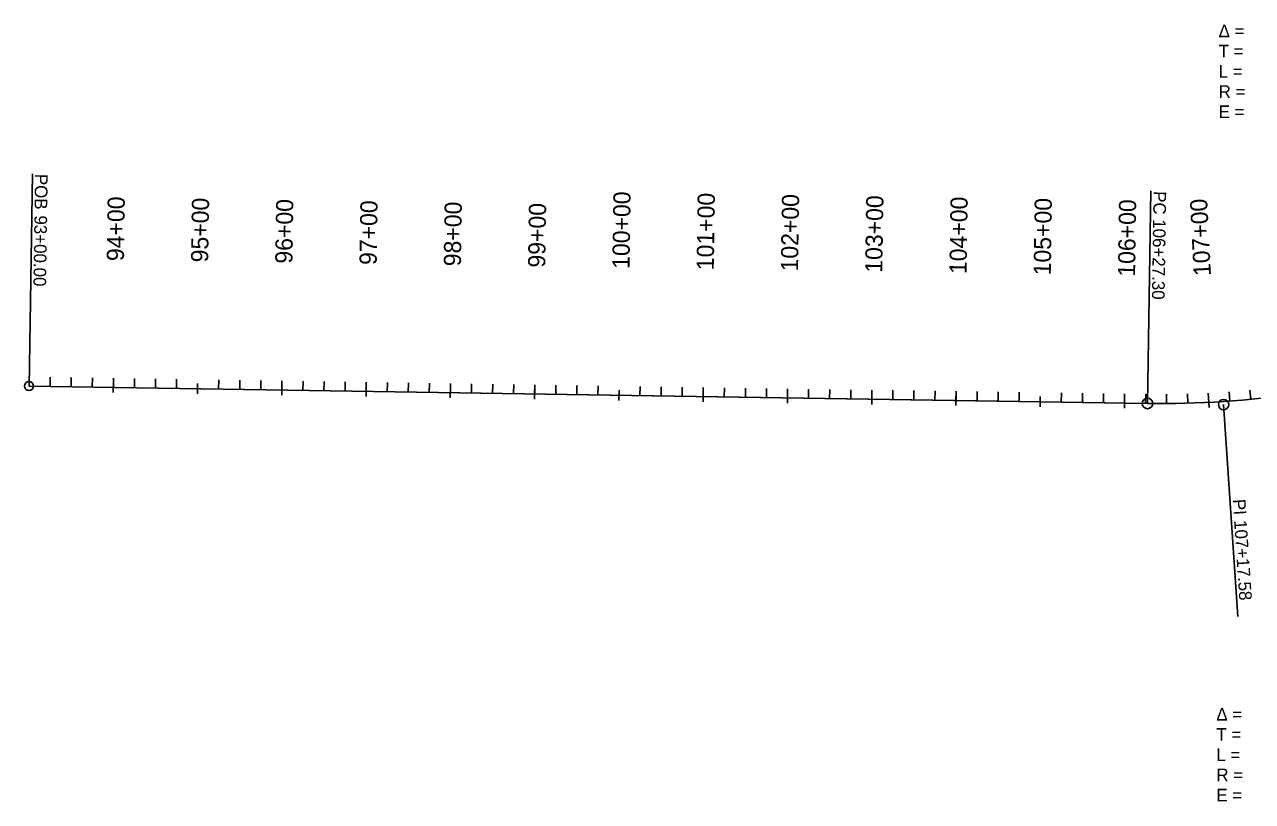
# Model space of a CAD drawing. Extents: x 20504372 to 20508399, y 7970077 to 7971028.
# Drawn here: x 20504372 to 20505829, y 7970077 to 7970999 of the extents above; entities that cross this region are included whole.
import ezdxf

# ---------------------------------------------------------------- set-up
doc = ezdxf.new("R2010")
doc.units = 0
for name, color, linetype in [('SurAlignment', 7, 'Continuous'), ('SurMiscNotes', 7, 'Continuous'), ('TextAlignment', 7, 'Continuous'), ('TextAlignmentSml', 7, 'Continuous')]:
    doc.layers.add(name, color=color, linetype=linetype)

msp = doc.modelspace()

# ---------------------------------------------------------------- linework, layer by layer
at = {"layer": 'SurAlignment'}
for q in [(20505654.4, 7970550.1), (20505704.3, 7970549.3)]:
    msp.add_line((20504377.2, 7970569.8), q, dxfattribs=at)
msp.add_arc((20505721.3, 7971649.2), 1100, 269.1162, 278.5003, dxfattribs=at)
msp.add_arc((20505721.3, 7971649.2), 1100, 269.1162, 278.5003, dxfattribs=at)
at = {"layer": 'SurMiscNotes'}
for p, q in [((20504477.2, 7970568.2), (20504477.3, 7970579.1)), ((20504577.2, 7970572.8), (20504577.1, 7970560.6)), ((20504677.1, 7970565.1), (20504677.3, 7970576)), ((20504777.1, 7970563.6), (20504777.3, 7970574.5)), ((20504877.1, 7970562), (20504877.3, 7970573)), ((20504977.1, 7970560.5), (20504977.3, 7970571.4)), ((20505077.2, 7970565.1), (20505077, 7970552.8)), ((20505177.1, 7970557.4), (20505177.2, 7970568.3)), ((20505277.1, 7970555.9), (20505277.2, 7970566.8)), ((20505377, 7970554.3), (20505377.2, 7970565.2)), ((20505477, 7970552.8), (20505477.2, 7970563.7)), ((20505577.1, 7970557.4), (20505576.9, 7970545.1)), ((20505677, 7970549.7), (20505677.2, 7970560.6)), ((20505777, 7970550.6), (20505776.4, 7970561.5))]:
    msp.add_line(p, q, dxfattribs=at)
at = {"layer": 'TextAlignment'}
for p, q in [((20504377.2, 7970569.8), (20504381.1, 7970821.7)), ((20504381.1, 7970821.7), (20504381.1, 7970821.7)), ((20505704.3, 7970549.3), (20505708.2, 7970801.3)), ((20505708.2, 7970801.3), (20505708.2, 7970801.3)), ((20505794.6, 7970547.9), (20505811.3, 7970296.4)), ((20505811.3, 7970296.4), (20505811.3, 7970296.4))]:
    msp.add_line(p, q, dxfattribs=at)
for centre, radius in [((20504377.2, 7970569.8), 5.34), ((20505704.3, 7970549.3), 6.24), ((20505794.6, 7970547.9), 6.24)]:
    msp.add_circle(centre, radius, dxfattribs=at)
at = {"layer": 'TextAlignmentSml'}
for p, q in [((20504402.2, 7970569.4), (20504402.3, 7970580.3)), ((20504427.2, 7970569), (20504427.3, 7970579.9)), ((20504452.2, 7970568.6), (20504452.3, 7970579.5)), ((20504502.2, 7970567.8), (20504502.3, 7970578.7)), ((20504527.2, 7970567.4), (20504527.3, 7970578.4)), ((20504552.1, 7970567.1), (20504552.3, 7970578)), ((20504477.3, 7970574.3), (20504477.1, 7970562.1)), ((20504577.2, 7970572.8), (20504577.1, 7970560.6)), ((20504602.1, 7970566.3), (20504602.3, 7970577.2)), ((20504627.1, 7970565.9), (20504627.3, 7970576.8)), ((20504652.1, 7970565.5), (20504652.3, 7970576.4)), ((20504677.2, 7970571.2), (20504677, 7970559)), ((20504702.1, 7970564.7), (20504702.3, 7970575.7)), ((20504727.1, 7970564.4), (20504727.3, 7970575.3)), ((20504752.1, 7970564), (20504752.3, 7970574.9)), ((20504777.2, 7970569.7), (20504777, 7970557.5)), ((20504802.1, 7970563.2), (20504802.3, 7970574.1)), ((20504827.1, 7970562.8), (20504827.3, 7970573.7)), ((20504852.1, 7970562.4), (20504852.3, 7970573.3)), ((20504877.2, 7970568.2), (20504877, 7970555.9)), ((20504902.1, 7970561.7), (20504902.3, 7970572.6)), ((20504927.1, 7970561.3), (20504927.3, 7970572.2)), ((20504952.1, 7970560.9), (20504952.3, 7970571.8)), ((20504977.2, 7970566.6), (20504977, 7970554.4)), ((20505002.1, 7970560.1), (20505002.3, 7970571)), ((20505027.1, 7970559.7), (20505027.3, 7970570.6)), ((20505052.1, 7970559.3), (20505052.3, 7970570.3)), ((20505077.2, 7970565.1), (20505077, 7970552.8)), ((20505102.1, 7970558.6), (20505102.3, 7970569.5)), ((20505127.1, 7970558.2), (20505127.2, 7970569.1)), ((20505152.1, 7970557.8), (20505152.2, 7970568.7)), ((20505177.2, 7970563.5), (20505177, 7970551.3)), ((20505202.1, 7970557), (20505202.2, 7970567.9)), ((20505227.1, 7970556.6), (20505227.2, 7970567.6)), ((20505252.1, 7970556.3), (20505252.2, 7970567.2)), ((20505302.1, 7970555.5), (20505302.2, 7970566.4)), ((20505327.1, 7970555.1), (20505327.2, 7970566)), ((20505352.1, 7970554.7), (20505352.2, 7970565.6)), ((20505402, 7970553.9), (20505402.2, 7970564.9)), ((20505427, 7970553.6), (20505427.2, 7970564.5)), ((20505452, 7970553.2), (20505452.2, 7970564.1)), ((20505502, 7970552.4), (20505502.2, 7970563.3)), ((20505826.8, 7970554.2), (20505825.8, 7970565.1)), ((20505277.2, 7970562), (20505277, 7970549.8)), ((20505377.1, 7970560.4), (20505377, 7970548.2)), ((20505477.1, 7970558.9), (20505476.9, 7970546.7)), ((20505527, 7970552), (20505527.2, 7970562.9)), ((20505552, 7970551.6), (20505552.2, 7970562.5)), ((20505577.1, 7970557.4), (20505576.9, 7970545.1)), ((20505602, 7970550.9), (20505602.2, 7970561.8)), ((20505627, 7970550.5), (20505627.2, 7970561.4)), ((20505652, 7970550.1), (20505652.2, 7970561)), ((20505677.1, 7970555.8), (20505676.9, 7970543.6)), ((20505702, 7970549.3), (20505702.2, 7970560.2)), ((20505727, 7970549.2), (20505727, 7970560.1)), ((20505752, 7970549.6), (20505751.7, 7970560.5)), ((20505776.7, 7970556.7), (20505777.3, 7970544.4)), ((20505801.9, 7970552.1), (20505801.1, 7970563))]:
    msp.add_line(p, q, dxfattribs=at)

# ---------------------------------------------------------------- texts
at = {"layer": 'SurMiscNotes'}
for s, p in [('100+00', (20505089.6, 7970708.8)), ('95+00', (20504589.7, 7970716.5)), ('105+00', (20505589.5, 7970701.1))]:
    msp.add_text(s, height=20.4, rotation=89.1162, dxfattribs=at).set_placement(p)
at = {"layer": 'TextAlignment'}
for s, p in [('Δ = ', (20505788.7, 7970983.7)), ('T = ', (20505788.7, 7970959.7)), ('L = ', (20505788.7, 7970935.7)), ('R = ', (20505788.7, 7970911.7)), ('E = ', (20505788.7, 7970887.7)), ('Δ = ', (20505786, 7970173.2)), ('T = ', (20505786, 7970149.2)), ('L = ', (20505786, 7970125.2)), ('R = ', (20505786, 7970101.2)), ('E = ', (20505786, 7970077.2))]:
    msp.add_text(s, height=15, dxfattribs=at).set_placement(p)
for s, rotation, p in [('POB ', 269.1162, (20504384.3, 7970821.7)), ('PC', 269.1162, (20505711.5, 7970801.2)), ('93+00.00', 269.1162, (20504383.6, 7970772.4)), ('106+27.30', 269.1162, (20505711, 7970767.9)), ('PI ', 273.8083, (20505805.4, 7970435.4)), ('107+17.58', 273.8083, (20505807, 7970410.4))]:
    msp.add_text(s, height=15, rotation=rotation, dxfattribs=at).set_placement(p)
at = {"layer": 'TextAlignmentSml'}
for s, rotation, p in [('100+00', 89.1162, (20505089.6, 7970708.8)), ('101+00', 89.1162, (20505189.6, 7970707.2)), ('102+00', 89.1162, (20505289.6, 7970705.7)), ('94+00', 89.1162, (20504489.7, 7970718)), ('95+00', 89.1162, (20504589.7, 7970716.5)), ('96+00', 89.1162, (20504689.6, 7970715)), ('97+00', 89.1162, (20504789.6, 7970713.4)), ('98+00', 89.1162, (20504889.6, 7970711.9)), ('99+00', 89.1162, (20504989.6, 7970710.3)), ('103+00', 89.1162, (20505389.6, 7970704.2)), ('104+00', 89.1162, (20505489.6, 7970702.6)), ('105+00', 89.1162, (20505589.5, 7970701.1)), ('106+00', 89.1162, (20505689.5, 7970699.5)), ('107+00', 92.9028, (20505779.6, 7970700.9))]:
    msp.add_text(s, height=20.4, rotation=rotation, dxfattribs=at).set_placement(p)

doc.saveas('drawing.dxf')
